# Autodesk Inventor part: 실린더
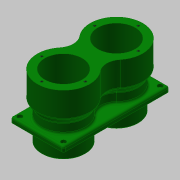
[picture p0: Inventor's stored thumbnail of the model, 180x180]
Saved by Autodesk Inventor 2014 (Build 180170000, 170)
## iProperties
Created: 2016-11
Part Number: 실린더
Material: 알루미늄 6061
Document SubType Name: Modeling
Designer: mduedu
Density: 2.71 g/cm^3
Mass: 1199.25 g
Surface Area: 1038.68 cm^2
Volume: 442.528 cm^3
Appearance: 진녹색
Author: mduedu
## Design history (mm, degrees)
sketch "스케치1"
  geometry: L1 (0, 0)-(0, 101); L2 (30, 0)-(30, 101); L3 (30, 101)-(42, 101); L4 (42, 101)-(42, 61); L5 (42, 61)-(35, 51); L6 (35, 51)-(35, 0); L7 (35, 0)-(30, 0)
  constraints: 14 end point, 4 parallel, 2 horizontal alignment, 1 perpendicular, 1 vertical
  dimensions: "d0" = 101 distance of L1.start L1.end; "d1" = 60 diameter of L2.end L1; "d2" = 84 diameter of L3.end L1; "d3" = 70 diameter of L6.end L1; "d4" = 40 distance of L3.end L4.end; "d5" = 50 vertical distance of L5.end L3.end
revolve "회전1" stored, may be unused: angle "d6" = 90 deg
node "작업 평면1"
sketch "스케치2"
  geometry: L1 (-42.5, -42.5)-(42.5, -42.5); L2 (42.5, -42.5)-(42.5, 42.5); L3 (42.5, 42.5)-(-42.5, 42.5); L4 (-42.5, 42.5)-(-42.5, -42.5); L5 (-42.5, -42.5)-(42.5, 42.5); L6 (42.5, -42.5)-(-42.5, 42.5); C1 r 35 at (0, 0) reference; C2 r 35 at (0, 0); 1 further point
  constraints: 12 end point, 2 midpoint, 2 parallel, 2 perpendicular, 1 centre point, 1 coincident, 1 concentric, 1 horizontal
  dimensions: "d8" = 85 distance of L2.end L3.end
extrude "돌출1" join sketch "스케치2" distance "d10" = 8; taper "d11" = 0 deg
chamfer "모따기1" distance "d14" = 1; stored, may be unused: second distance "d15" = 2, angle "d16" = 45 deg
chamfer "모따기2" distance "d17" = 5; stored, may be unused: second distance "d18" = 2, angle "d19" = 15 deg
sketch "스케치3"
  geometry: L1 (-35, -35)-(35, -35); L2 (35, -35)-(35, 35); L3 (35, 35)-(-35, 35); L4 (-35, 35)-(-35, -35); L5 (-35, -35)-(35, 35); L6 (35, -35)-(-35, 35); 3 further points
  constraints: 12 end point, 2 coincident, 2 midpoint, 2 parallel, 1 horizontal, 1 perpendicular
  dimensions: "d20" = 70 distance of L3.end L2.end; "d21" = 70 distance of L2.end L1.end
sketch "스케치4"
  geometry: 2 further points
  constraints: 2 other
hole "구멍1" sketch "스케치4" at (-35, 35), (35, 35) diameter "d22" = 4.5; stored, may be unused: countersink angle "d26" = 90 deg, drill point angle "d28" = 0 deg; dims "d23" = 6, "d24" = 8, "d25" = 4.6, "d27" = 8
sketch "스케치5"
  geometry: 3 further points
  constraints: 3 other
hole "구멍2" sketch "스케치5" at (35, 0), (-35, 0), (0, 35) diameter "d29" = 4.134; stored, may be unused: countersink angle "d33" = 90 deg, drill point angle "d35" = 120 deg; dims "d30" = 7.5, "d31" = 4, "d32" = 2, "d34" = 10
fillet "모깎기3" dims "d36" = 3
fillet "모깎기4" dims "d37" = 3
sketch "스케치6"
  geometry: L1 (0, 0)-(0, -85); A1 r 42 centre (0, 0) between (32.469, -26.642) and (-32.469, -26.642) reference; A2 r 42 centre (0, -85) between (32.469, -58.358) and (-32.469, -58.358) reference; A3 r 25 centre (51.795, -42.5) between (32.469, -58.358) and (32.469, -26.642); A4 r 25 centre (-51.795, -42.5) between (-32.469, -26.642) and (-32.469, -58.358); A5 r 25 centre (51.795, -42.5) between (32.469, -26.642) and (32.469, -58.358); A6 r 25 centre (-51.795, -42.5) between (-32.469, -58.358) and (-32.469, -26.642); A7 r 42 centre (0, 0) between (-32.469, -26.642) and (32.469, -26.642); A8 r 42 centre (0, -85) between (32.469, -58.358) and (-32.469, -58.358); A9 r 42 centre (0, 0) between (32.469, -26.642) and (-32.469, -26.642); A10 r 42 centre (0, -85) between (-32.469, -58.358) and (32.469, -58.358); 1 further point
  constraints: 20 point on circle, 8 centre point, 2 coincident, 2 end point, 2 tangent, 1 symmetric about line, 1 vertical, 1 other
  dimensions: "d38" = 50 diameter of A3
node "작업 평면2"
sketch "스케치7"
  geometry: A1 r 25 centre (9.795, -42.5) between (-9.531, -26.642) and (-9.531, -58.358) reference; A2 r 42 centre (-42, 0) between (-74.469, -26.642) and (-9.531, -26.642) reference; A3 r 42 centre (-42, -85) between (-9.531, -58.358) and (-74.469, -58.358) reference; A4 r 25 centre (-93.795, -42.5) between (-74.469, -58.358) and (-74.469, -26.642) reference; 1 further point
node "작업 평면3"
sketch "스케치8"
  geometry: L1 (-35, 0)-(-35, -85); A1 r 35 centre (-35, 0) between (-10.294, -24.792) and (-59.706, -24.792) reference; A2 r 35 centre (-35, -85) between (-10.294, -60.208) and (-59.706, -60.208) reference; A3 r 25 centre (7.353, -42.5) between (-10.294, -60.208) and (-10.294, -24.792); A4 r 25 centre (-77.353, -42.5) between (-59.706, -24.792) and (-59.706, -60.208); A5 r 25 centre (7.353, -42.5) between (-10.294, -24.792) and (-10.294, -60.208); A6 r 25 centre (-77.353, -42.5) between (-59.706, -60.208) and (-59.706, -24.792); A7 r 35 centre (-35, 0) between (-59.706, -24.792) and (-10.294, -24.792); A8 r 35 centre (-35, -85) between (-10.294, -60.208) and (-59.706, -60.208); 1 further point
  constraints: 16 point on circle, 6 centre point, 2 coincident, 2 end point, 2 tangent, 1 symmetric about line, 1 vertical, 1 other
  dimensions: "d40" = 50 diameter of A3
sketch "스케치9"
  geometry: A1 r 25 centre (42.353, -42.5) between (24.706, -24.792) and (24.706, -60.208) reference; A2 r 35 centre (0, 0) between (-24.706, -24.792) and (24.706, -24.792) reference; A3 r 35 centre (0, -85) between (24.706, -60.208) and (-24.706, -60.208) reference; A4 r 25 centre (-42.353, -42.5) between (-24.706, -60.208) and (-24.706, -24.792) reference; 1 further point
feature "로프트1" sketch "스케치8", "스케치9" dims "d42" = 0, "d43" = 90 deg, "d44" = 0, "d45" = 90 deg
feature "로프트2" dims "d46" = 0, "d47" = 90 deg, "d48" = 0, "d49" = 90 deg
  node "모서리1"
feature "로프트3" dims "d50" = 0, "d51" = 90 deg, "d52" = 0, "d53" = 90 deg
  node "모서리2"
fillet "모깎기5" dims "d54" = 3
node "솔리드1"
mirror "대칭1"
other parameters: "d7" = -27
